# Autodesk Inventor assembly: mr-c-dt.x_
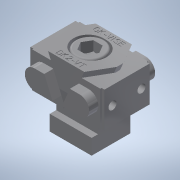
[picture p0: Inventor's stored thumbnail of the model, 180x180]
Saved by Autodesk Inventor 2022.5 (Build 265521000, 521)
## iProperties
Part Number: mr-c-dt.x_
Material: 一般
Document SubType Name: Assembly
Designer: ImaoCorp
Sending System: SOLIDWORKS 2017-2017317
MC: AMD64
MC_MODEL: Intel64 Family 6 Model 60 Stepping 3, GenuineIntel
OS: Windows_NT
FRU: Parasolid Version 29.0, build 201,  4-17-2017
FORMAT: text
GUISE: transmit
KEY: mr-c-dt
FILE: mr-c-dt.x_t
DATE: Fri Jul 26 11:48:35 2019
Author: ImaoCorp
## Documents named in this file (5)
- X:\14_SW2022-Inv2022\00_全2023-1023新製品(TCC)まで\m\mr-c-dt\MR-C-DT.iam
- X:\14_SW2022-Inv2022\00_全2023-1023新製品(TCC)まで\m\mr-c-dt\mr-c-dt_01.ipt
- X:\14_SW2022-Inv2022\00_全2023-1023新製品(TCC)まで\m\mr-c-dt\mr-c-dt_02.ipt
- X:\14_SW2022-Inv2022\00_全2023-1023新製品(TCC)まで\m\mr-c-dt\mr-c-dt_03.ipt
- X:\14_SW2022-Inv2022\00_全2023-1023新製品(TCC)まで\m\mr-c-dt\mr-c-dt_04.ipt
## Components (4 placed, 4 different names)
1. mr-c-dt_01
2. mr-c-dt_02
3. mr-c-dt_03
4. mr-c-dt_04
